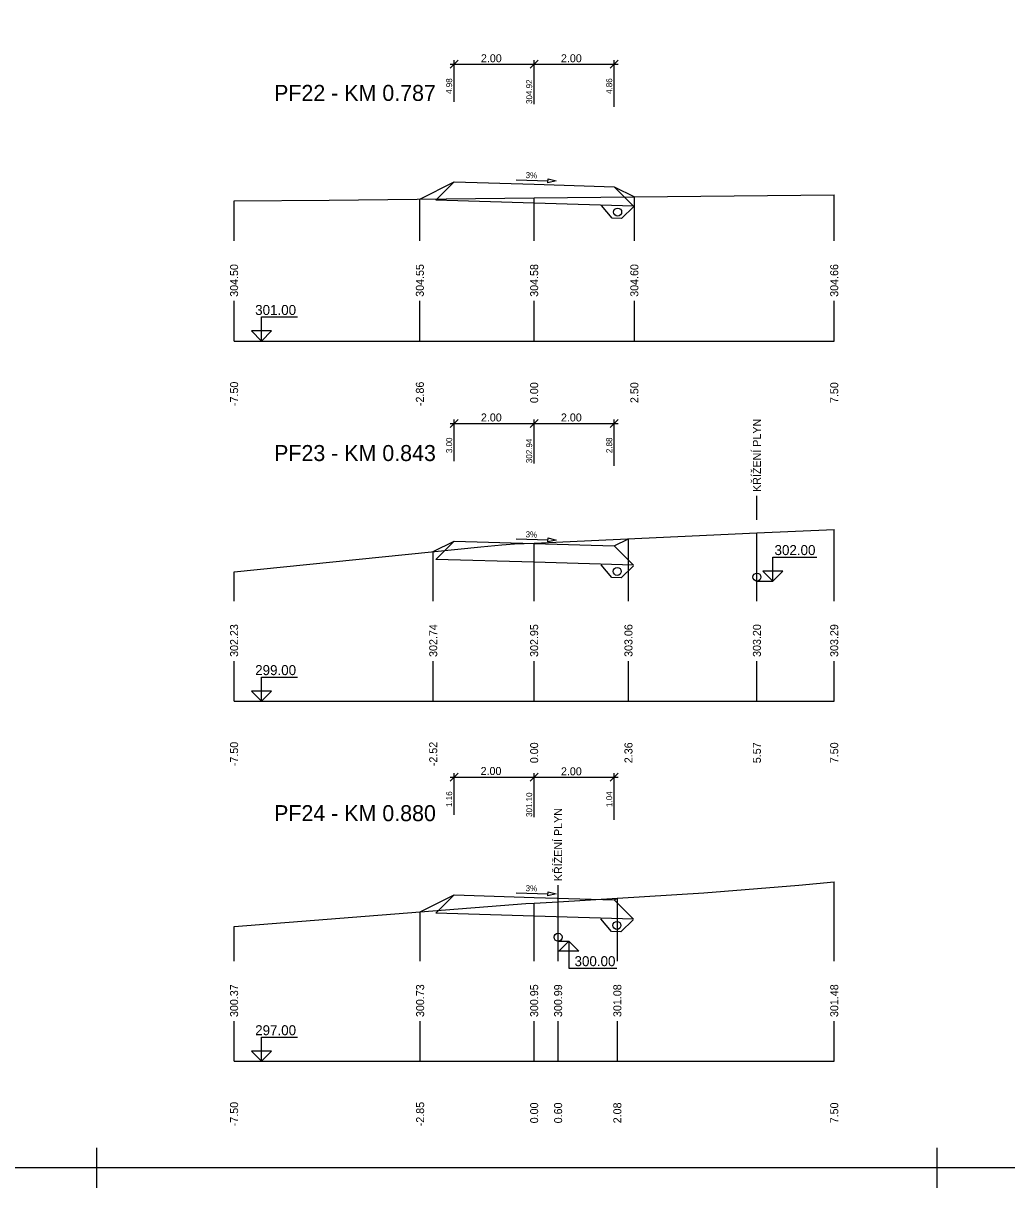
# Model space of a CAD drawing. Extents: x -9 to 2311, y -2 to 597.
# Drawn here: x 1447.3 to 1693.1, y -1.6 to 289.4 of the extents above; entities that cross this region are included whole.
import ezdxf

# ---------------------------------------------------------------- set-up
doc = ezdxf.new("R2010")
doc.units = 0
for name, color, linetype in [('KOTA', 7, 'Continuous'), ('KOTA_DELKY', 7, 'Continuous'), ('KOTA_DELKY_CONT', 7, 'Continuous'), ('KRIZENI', 7, 'Continuous'), ('NS_TELESO_VOZOVKY', 7, 'Continuous'), ('NS_V_PF', 7, 'Continuous'), ('POPISY_NAD_TERENEM', 7, 'Continuous'), ('REZY_PF_PUVODNI', 7, 'Continuous'), ('SESTAVY_REZU_PF', 7, 'Continuous'), ('SKLON', 7, 'Continuous'), ('SVK', 7, 'Continuous'), ('SVK_STAT', 7, 'Continuous')]:
    doc.layers.add(name, color=color, linetype=linetype)

msp = doc.modelspace()

# ---------------------------------------------------------------- linework, layer by layer
for p, q in [((1465.65, 8.39), (1465.65, -1.61)), ((1465.65, 8.39), (1465.65, -1.61)), ((1465.65, 8.39), (1465.65, -1.61)), ((1465.65, 8.39), (1465.65, -1.61)), ((1465.65, 8.39), (1465.65, -1.61)), ((1465.65, 8.39), (1465.65, -1.61)), ((1465.65, 8.39), (1465.65, -1.61)), ((1465.65, 8.39), (1465.65, -1.61)), ((1465.65, 8.39), (1465.65, -1.61)), ((1465.65, 8.39), (1465.65, -1.61)), ((1465.65, 8.39), (1465.65, -1.61)), ((1465.65, 8.39), (1465.65, -1.61)), ((1675.65, 8.39), (1675.65, -1.61)), ((1675.65, 8.39), (1675.65, -1.61)), ((1675.65, 8.39), (1675.65, -1.61)), ((1675.65, 8.39), (1675.65, -1.61)), ((1675.65, 8.39), (1675.65, -1.61)), ((1675.65, 8.39), (1675.65, -1.61)), ((1675.65, 8.39), (1675.65, -1.61)), ((1675.65, 8.39), (1675.65, -1.61)), ((1675.65, 8.39), (1675.65, -1.61)), ((1675.65, 8.39), (1675.65, -1.61)), ((1675.65, 8.39), (1675.65, -1.61)), ((1675.65, 8.39), (1675.65, -1.61)), ((1470.65, 3.39), (1460.65, 3.39)), ((1470.65, 3.39), (1460.65, 3.39)), ((1470.65, 3.39), (1460.65, 3.39)), ((1470.65, 3.39), (1460.65, 3.39)), ((1470.65, 3.39), (1460.65, 3.39)), ((1470.65, 3.39), (1460.65, 3.39)), ((1470.65, 3.39), (1460.65, 3.39)), ((1470.65, 3.39), (1460.65, 3.39)), ((1470.65, 3.39), (1460.65, 3.39)), ((1470.65, 3.39), (1460.65, 3.39)), ((1470.65, 3.39), (1460.65, 3.39)), ((1470.65, 3.39), (1460.65, 3.39)), ((1680.65, 3.39), (1670.65, 3.39)), ((1680.65, 3.39), (1670.65, 3.39)), ((1680.65, 3.39), (1670.65, 3.39)), ((1680.65, 3.39), (1670.65, 3.39)), ((1680.65, 3.39), (1670.65, 3.39)), ((1680.65, 3.39), (1670.65, 3.39)), ((1680.65, 3.39), (1670.65, 3.39)), ((1680.65, 3.39), (1670.65, 3.39)), ((1680.65, 3.39), (1670.65, 3.39)), ((1680.65, 3.39), (1670.65, 3.39)), ((1680.65, 3.39), (1670.65, 3.39)), ((1680.65, 3.39), (1670.65, 3.39))]:
    msp.add_line(p, q)
msp.add_lwpolyline([(-4.35, 597.39), (2305.65, 597.39), (2305.65, 3.39), (-4.35, 3.39)], close=True)
for points in [[(1599.93, 243.64), (1596.87, 240.6), (1594.53, 240.7), (1591.82, 243.84)], [(1599.81, 153.83), (1596.76, 150.79), (1594.42, 150.89), (1591.71, 154.03)], [(1599.75, 65.35), (1596.7, 62.31), (1594.35, 62.41), (1591.64, 65.55)]]:
    msp.add_lwpolyline(points)
for centre in [(1595.87, 242.23), (1595.76, 152.43), (1595.69, 63.95)]:
    msp.add_circle(centre, 1)
at = {"layer": 'KOTA'}
for points in [[(1506.85, 212.5), (1504.35, 212.5), (1506.85, 210), (1506.85, 216), (1515.85, 216)], [(1506.85, 210), (1509.35, 212.5), (1506.85, 212.5)], [(1634.67, 152.5), (1632.17, 152.5), (1634.67, 150), (1634.67, 156), (1645.67, 156)], [(1634.67, 152.5), (1632.17, 152.5), (1634.67, 150), (1634.67, 156), (1645.67, 156)], [(1630.67, 150), (1634.67, 150), (1637.17, 152.5), (1634.67, 152.5)], [(1630.67, 150), (1634.67, 150), (1637.17, 152.5), (1634.67, 152.5)], [(1506.85, 122.5), (1504.35, 122.5), (1506.85, 120), (1506.85, 126), (1515.85, 126)], [(1506.85, 120), (1509.35, 122.5), (1506.85, 122.5)], [(1580.99, 60), (1583.69, 60), (1586.19, 57.5), (1583.69, 57.5)], [(1583.69, 57.5), (1581.19, 57.5), (1583.69, 60), (1583.69, 53.26), (1595.68, 53.26)], [(1506.85, 32.5), (1504.35, 32.5), (1506.85, 30), (1506.85, 36), (1515.85, 36)], [(1506.85, 30), (1509.35, 32.5), (1506.85, 32.5)]]:
    msp.add_lwpolyline(points, dxfattribs=at)
at = {"layer": 'KOTA_DELKY'}
for points in [[(1554, 278.16), (1556, 280.16)], [(1555, 269.76), (1555, 280.16)], [(1574, 278.16), (1576, 280.16)], [(1574, 278.16), (1576, 280.16)], [(1575, 269.16), (1575, 280.16)], [(1575, 269.16), (1575, 280.16)], [(1594, 278.16), (1596, 280.16)], [(1595, 268.56), (1595, 280.16)], [(1554, 279.16), (1576, 279.16)], [(1574, 279.16), (1596, 279.16)], [(1554, 188.39), (1556, 190.39)], [(1554, 189.39), (1576, 189.39)], [(1555, 179.99), (1555, 190.39)], [(1574, 188.39), (1576, 190.39)], [(1574, 188.39), (1576, 190.39)], [(1574, 189.39), (1596, 189.39)], [(1575, 179.39), (1575, 190.39)], [(1575, 179.39), (1575, 190.39)], [(1594, 188.39), (1596, 190.39)], [(1595, 178.79), (1595, 190.39)], [(1554, 99.96), (1556, 101.96)], [(1555, 91.56), (1555, 101.96)], [(1574, 99.96), (1576, 101.96)], [(1574, 99.96), (1576, 101.96)], [(1575, 90.96), (1575, 101.96)], [(1575, 90.96), (1575, 101.96)], [(1594, 99.96), (1596, 101.96)], [(1595, 90.36), (1595, 101.96)], [(1554, 100.96), (1576, 100.96)], [(1574, 100.96), (1596, 100.96)]]:
    msp.add_lwpolyline(points, dxfattribs=at)
at = {"layer": 'KRIZENI'}
for centre in [(1630.67, 151), (1580.99, 61)]:
    msp.add_circle(centre, 1, dxfattribs=at)
at = {"layer": 'NS_TELESO_VOZOVKY'}
for points in [[(1575, 249.16), (1595, 248.56), (1595, 248.56), (1599.85, 243.71), (1575, 244.46), (1550.44, 245.19), (1555, 249.76), (1555, 249.76), (1575, 249.16)], [(1575, 159.39), (1595, 158.79), (1595, 158.79), (1599.85, 153.94), (1575, 154.69), (1550.44, 155.43), (1555, 159.99), (1555, 159.99), (1575, 159.39)], [(1575, 70.96), (1595, 70.36), (1595, 70.36), (1599.85, 65.51), (1575, 66.26), (1550.44, 67), (1555, 71.56), (1555, 71.56), (1575, 70.96)]]:
    msp.add_lwpolyline(points, dxfattribs=at)
at = {"layer": 'NS_V_PF'}
for points in [[(1546.43, 245.47), (1555, 249.76), (1555, 249.76), (1575, 249.16), (1595, 248.56), (1595, 248.56), (1600.04, 246.04)], [(1549.77, 157.38), (1555, 159.99), (1555, 159.99), (1575, 159.39), (1595, 158.79), (1595, 158.79), (1598.57, 160.57)], [(1546.5, 67.31), (1555, 71.56), (1555, 71.56), (1575, 70.96), (1595, 70.36), (1595, 70.36), (1595.79, 70.75)]]:
    msp.add_lwpolyline(points, dxfattribs=at)
at = {"layer": 'POPISY_NAD_TERENEM'}
for points in [[(1630.67, 165.28), (1630.67, 171.28)], [(1580.99, 68), (1580.99, 74)]]:
    msp.add_lwpolyline(points, dxfattribs=at)
at = {"layer": 'REZY_PF_PUVODNI'}
for points in [[(1500, 244.99), (1523.74, 245.23), (1575, 245.77), (1650, 246.56)], [(1500, 152.29), (1561.71, 158.59), (1566.89, 159.07), (1570.05, 159.27), (1575, 159.5), (1630.67, 162.04), (1650, 162.92)], [(1500, 63.66), (1572.9, 69.38), (1575, 69.51), (1575, 69.51), (1580.99, 69.87), (1617.37, 72.05), (1641.13, 74.04), (1650, 74.83)]]:
    msp.add_lwpolyline(points, dxfattribs=at)
at = {"layer": 'SESTAVY_REZU_PF'}
for points in [[(1500, 210), (1650, 210)], [(1500, 120), (1650, 120)], [(1500, 30), (1650, 30)]]:
    msp.add_lwpolyline(points, dxfattribs=at)
at = {"layer": 'SKLON'}
for points in [[(1570.47, 250.29), (1578.47, 250.05)], [(1578.48, 250.55), (1580.47, 249.99), (1578.45, 249.55), (1578.48, 250.55)], [(1570.47, 160.53), (1578.47, 160.29)], [(1578.48, 160.79), (1580.47, 160.23), (1578.45, 159.79), (1578.48, 160.79)], [(1570.47, 72.1), (1578.47, 71.86)], [(1578.48, 72.36), (1580.47, 71.8), (1578.45, 71.36), (1578.48, 72.36)]]:
    msp.add_lwpolyline(points, dxfattribs=at)
at = {"layer": 'SVK'}
for points in [[(1500, 235), (1500, 244.99)], [(1546.43, 235), (1546.43, 245.47)], [(1575, 235), (1575, 245.77)], [(1600.04, 235), (1600.04, 246.04)], [(1650, 235), (1650, 246.56)], [(1500, 210), (1500, 220)], [(1546.43, 210), (1546.43, 220)], [(1575, 210), (1575, 220)], [(1600.04, 210), (1600.04, 220)], [(1650, 210), (1650, 220)], [(1598.57, 145), (1598.57, 160.57)], [(1650, 145), (1650, 162.92)], [(1549.77, 145), (1549.77, 157.38)], [(1575, 145), (1575, 159.5)], [(1500, 145), (1500, 152.29)], [(1500, 120), (1500, 130)], [(1549.77, 120), (1549.77, 130)], [(1575, 120), (1575, 130)], [(1598.57, 120), (1598.57, 130)], [(1650, 120), (1650, 130)], [(1650, 55), (1650, 74.83)], [(1595.79, 55), (1595.79, 70.75)], [(1546.5, 55), (1546.5, 67.31)], [(1575, 55), (1575, 69.51)], [(1500, 55), (1500, 63.66)], [(1500, 30), (1500, 40)], [(1546.5, 30), (1546.5, 40)], [(1575, 30), (1575, 40)], [(1595.79, 30), (1595.79, 40)], [(1650, 30), (1650, 40)]]:
    msp.add_lwpolyline(points, dxfattribs=at)
at = {"layer": 'SVK_STAT'}
for points in [[(1630.67, 145), (1630.67, 162.04)], [(1630.67, 120), (1630.67, 130)], [(1580.99, 55), (1580.99, 69.87)], [(1580.99, 30), (1580.99, 40)]]:
    msp.add_lwpolyline(points, dxfattribs=at)

# ---------------------------------------------------------------- texts
at = {"layer": 'KOTA'}
for s, p in [('301.00', (1505.27, 216.5)), ('302.00', (1635.08, 156.5)), ('302.00', (1635.08, 156.5)), ('299.00', (1505.27, 126.5)), ('300.00', (1585.09, 53.76)), ('297.00', (1505.27, 36.5))]:
    msp.add_text(s, height=2.5, dxfattribs=at).set_placement(p)
at = {"layer": 'KOTA_DELKY'}
for p in [(1561.69, 279.66), (1581.69, 279.66), (1561.69, 189.89), (1581.69, 189.89), (1561.61, 101.54), (1581.69, 101.46)]:
    msp.add_text('2.00', height=2, dxfattribs=at).set_placement(p)
at = {"layer": 'KOTA_DELKY_CONT'}
for s, p in [('4.98', (1554.5, 271.75)), ('304.92', (1574.5, 269.23)), ('4.86', (1594.5, 271.75)), ('3.00', (1554.5, 181.98)), ('302.94', (1574.5, 179.47)), ('2.88', (1594.5, 181.98)), ('1.16', (1554.5, 93.55)), ('301.10', (1574.5, 91.04)), ('1.04', (1594.5, 93.55))]:
    msp.add_text(s, height=1.5, rotation=90, dxfattribs=at).set_placement(p)
at = {"layer": 'POPISY_NAD_TERENEM'}
for p in [(1631.67, 172.28), (1581.99, 75)]:
    msp.add_text('KŘÍŽENÍ PLYN', height=2, rotation=90, dxfattribs=at).set_placement(p)
at = {"layer": 'SESTAVY_REZU_PF'}
for s, p in [('PF22 - KM 0.787', (1510, 270)), ('PF23 - KM 0.843', (1510, 180)), ('PF24 - KM 0.880', (1510, 90))]:
    msp.add_text(s, height=4, dxfattribs=at).set_placement(p)
at = {"layer": 'SKLON'}
for p in [(1572.84, 250.72), (1572.84, 160.95), (1572.84, 72.52)]:
    msp.add_text('3%', height=1.5, rotation=358.2816, dxfattribs=at).set_placement(p)
at = {"layer": 'SVK'}
for s, p in [(' 304.50', (1501, 220.3)), (' 304.55', (1547.43, 220.3)), (' 304.58', (1576, 220.3)), (' 304.60', (1601.04, 220.3)), (' 304.66', (1651, 220.3)), (' -7.50', (1501, 193)), (' -2.86', (1547.43, 193)), ('  0.00', (1576, 193)), ('  2.50', (1601.04, 193)), ('  7.50', (1651, 193)), (' 302.23', (1501, 130.3)), (' 302.74', (1550.77, 130.3)), (' 302.95', (1576, 130.3)), (' 303.06', (1599.57, 130.3)), (' 303.29', (1651, 130.3)), (' -7.50', (1501, 103)), (' -2.52', (1550.77, 103)), ('  0.00', (1576, 103)), ('  2.36', (1599.57, 103)), ('  7.50', (1651, 103)), (' 300.37', (1501, 40.3)), (' 300.73', (1547.5, 40.3)), (' 300.95', (1576, 40.3)), (' 301.08', (1596.79, 40.3)), (' 301.48', (1651, 40.3)), (' -7.50', (1501, 13)), (' -2.85', (1547.5, 13)), ('  0.00', (1576, 13)), ('  2.08', (1596.79, 13)), ('  7.50', (1651, 13))]:
    msp.add_text(s, height=2, rotation=90, dxfattribs=at).set_placement(p)
at = {"layer": 'SVK_STAT'}
for s, p in [(' 303.20', (1631.67, 130.3)), ('  5.57', (1631.67, 103)), (' 300.99', (1581.99, 40.3)), ('  0.60', (1581.99, 13))]:
    msp.add_text(s, height=2, rotation=90, dxfattribs=at).set_placement(p)

doc.saveas('drawing.dxf')
